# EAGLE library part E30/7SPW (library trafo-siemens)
TRANSFORMER
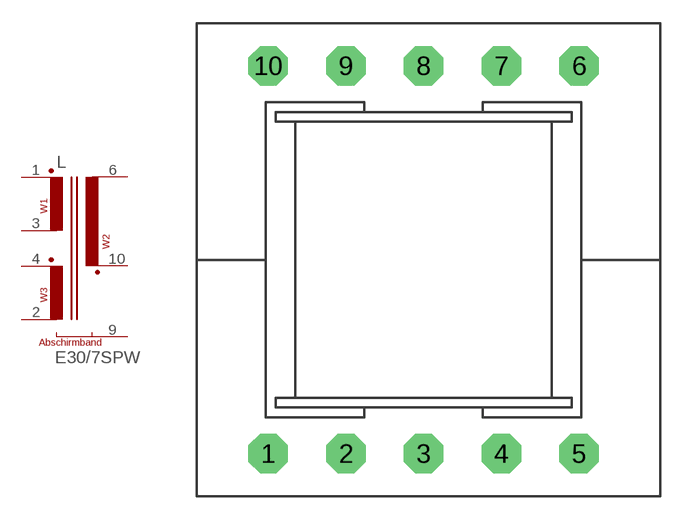
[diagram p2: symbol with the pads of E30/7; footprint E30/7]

Designator prefix L

## E30/7SPW  [E30/7]
1  1A  pas
2  3E  pas
3  1E  pas
4  3A  pas
6  2E  pas
9  SCH  pas
10  2A  pas

## Footprint E30/7 (pad centres in mm)
TRANSFORMER
drill 1.016 pad 2.54 octagon: 1 -10.008,-12.497; 2 -5.004,-12.497; 3 0,-12.497; 4 5.004,-12.497; 5 10.008,-12.497; 6 10.008,12.497; 7 5.004,12.497; 8 0,12.497; 9 -5.004,12.497; 10 -10.008,12.497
